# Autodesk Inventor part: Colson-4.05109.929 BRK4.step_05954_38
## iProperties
Created: 2010-10
Part Number: Colson-4.05109.929 BRK4.step_05954_38
Document SubType Name: Modeling
Designer: Administrator
Density: 7.85 g/cm^3
Material: Steel
Mass: 95.8183 g
Surface Area: 62.0581 cm^2
Volume: 12.2062 cm^3
Author: Administrator
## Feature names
1. Base1
